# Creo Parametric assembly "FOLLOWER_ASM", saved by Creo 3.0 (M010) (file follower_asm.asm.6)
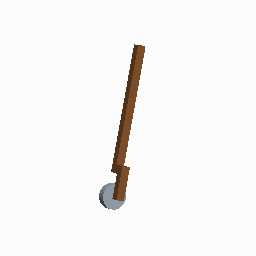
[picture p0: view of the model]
Units: millimeter Kilogram Sec (mmKs); MM, KILOGRAM, SECS

Created from: MMKS_ASM_DESIGN.ASM

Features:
  1. datum plane "ASM_RIGHT"
  2. datum plane "ASM_TOP"
  3. datum plane "ASM_FRONT"
  4. coordinate system
  5. component "FOLLOWER_BAR"
  6. component "FOLLOWER_ROLLER"

Family table entries: GENERIC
